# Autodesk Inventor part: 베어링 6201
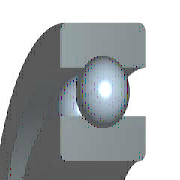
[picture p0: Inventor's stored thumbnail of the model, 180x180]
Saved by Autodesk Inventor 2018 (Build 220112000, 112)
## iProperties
IsCustomPart: 1
Created: 2012-02
Part Number: 베어링 6201
Material: 강철, 연강
Description: 깊은 그루브 볼 베어링
Document SubType Name: Modeling
Standard: KS B 2023
Designer: test
Standards Organization: KS
Language: ko-KR
Size Designation: 6201 - 12 x 32 x 10
Categories: <MemberInstance><Categories><Category DisplayName="샤프트 부품" InternalName="7f7aeb1f-a693-4053-b835-cee3144e0d98" Mnemonic="SHFT"><Category DisplayName="베어링" Inter
Density: 1 g/cm^3
Appearance: 노란색
Author: test
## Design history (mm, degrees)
sketch "스케치" dims "d0" = 5.2 (= -0.26 x WD + 0.26 x BD)
  geometry: L1 (2.4, 11)-(7.6, 11); L2 (5, 11)-(5, 8.4); L3 (5, 11)-(5, 13.6); L4 (3.068, 9.26)-(0, 9.26); L5 (0, 6)-(10, 6); L6 (3.068, 12.74)-(0, 12.74); L7 (0, 16)-(10, 16); L8 (10, 6)-(10, 9.26); L9 (6.932, 9.26)-(10, 9.26); L10 (6.932, 12.74)-(10, 12.74); L11 (10, 16)-(10, 12.74); L12 (-1.4, 0)-(8.4, 0) reference; L13 (0, -0.3)-(0, 5.3) reference
  constraints: 22 end point, 4 point on line, 2 collinear, 2 perpendicular, 2 symmetric about line, 1 midpoint, 1 parallel, 14 other
  dimensions: "d9" = 12 diameter of L5 L12 (= WD); "d11" = 32 diameter of L7 L12 (= BD); "d12" = 10 distance between parallel lines of L8 L13 (= KB); "d13" = 18.52 diameter of L9 L12 (= 0.326 x BD + 0.674 x WD)
revolve "본체" stored, may be unused: angle "d6" = 90 deg
revolve "볼" stored, may be unused: angle "d7" = 90 deg
pattern_circular "IDS_ARRAYBALL[SIMPL:T]" dims angle "d3" = 360 deg
body "Solid1"
fillet "모깎기1" dims "d1" = 0.6 (= KRS)
other parameters: "WD" = 12 [user parameter; used in 5 equation terms], "BD" = 32 [user parameter; used in 5 equation terms], "KB" = 10 [user parameter; used in 1 equation term], "KRS" = 0.6 [user parameter; used in 1 equation term], "d4" = 0, "d5" = 0, "d8" = 0, "d14" = 0, "d15" = 0, "BBA" = 0 [user parameter], "BC0" = 3100000 [user parameter], "BC" = 6890000 [user parameter], "BR" = 16 (= 0.5 x BD) [user parameter], "WR" = 6 (= 0.5 x WD) [user parameter]
